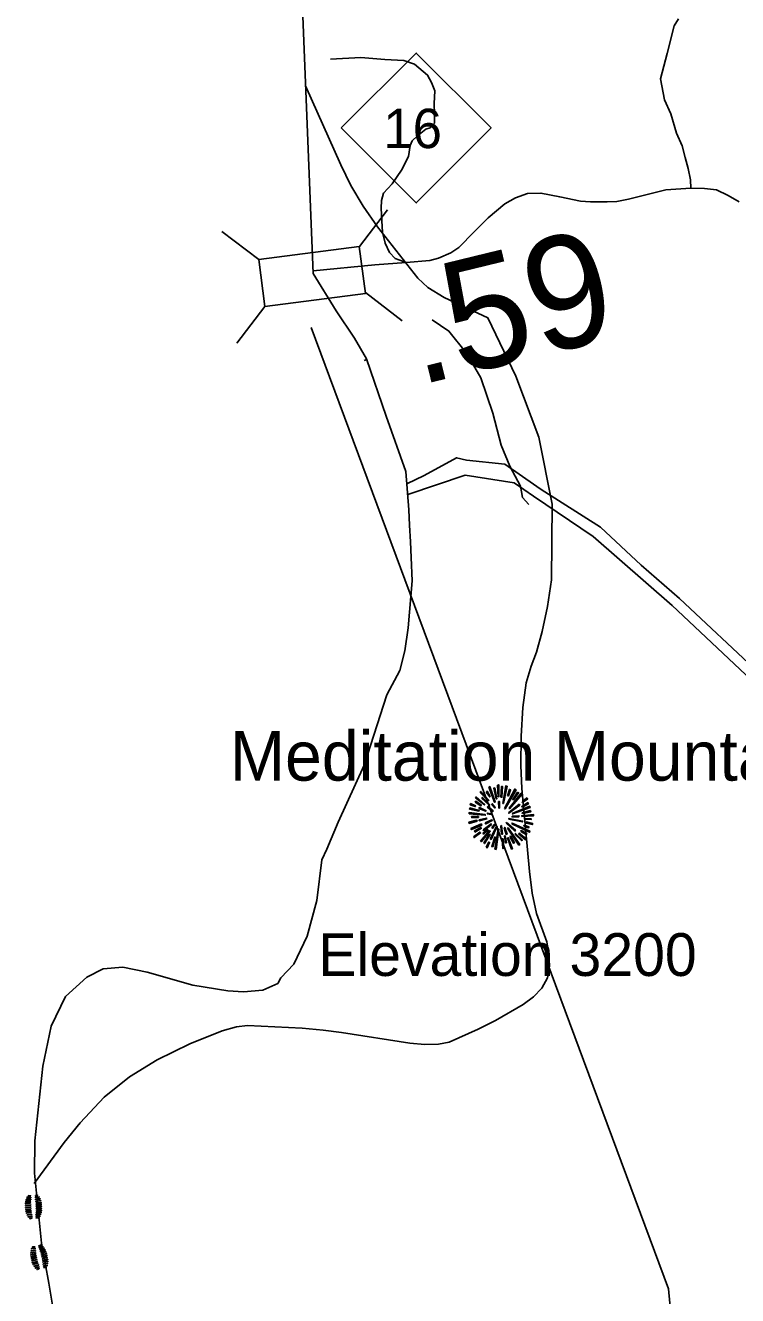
# Model space of a CAD drawing. Extents: x 1248089 to 1457196, y 820910 to 988753.
# Drawn here: x 1302535 to 1305699, y 936672 to 942316 of the extents above; entities that cross this region are included whole.
import ezdxf

# ---------------------------------------------------------------- set-up
doc = ezdxf.new("R2010")
doc.units = 0
for name, color, linetype in [('Exist Boundary Political CountyLine', 7, 'Continuous'), ('Exist Geographical Mountain Gap CELL', 7, 'Continuous'), ('Exist Geographical Mountain Summit CELL', 7, 'Continuous'), ('Exist Geographical Mountain Summit Elevation Number Label', 7, 'Continuous'), ('Exist Geographical Mountain Summit Label', 7, 'Continuous'), ('Exist Hydrographic Misc Water Feature', 7, 'Continuous'), ('Exist Road Blue Ridge Parkway', 7, 'Continuous'), ('Exist Road Blue Ridge Parkway Structure', 7, 'Continuous'), ('Exist Road Blue Ridge Parkway Structure Label', 7, 'Continuous'), ('Exist Road Non-System Type 51', 7, 'Continuous'), ('Exist Road Primary NC Attributed', 7, 'Continuous'), ('Exist Road Primary NC Shield CELL', 7, 'Continuous'), ('Exist Road Primary NC Shield Number Label', 7, 'Continuous'), ('Exist Utilities Electrical Transmission Line', 7, 'Continuous'), ('Prop CMT Slope Fill', 7, 'Continuous')]:
    doc.layers.add(name, color=color, linetype=linetype)

msp = doc.modelspace()

# ---------------------------------------------------------------- linework, layer by layer
at = {"layer": 'Exist Boundary Political CountyLine'}
for points in [[(1303813.5, 941214.4), (1303141.5, 957948.5)], [(1302662.3, 936594.3), (1302639.3, 936727.1), (1302606.5, 936905.1), (1302575.3, 937216), (1302577, 937359.5), (1302612.8, 937691.5), (1302649, 937869.2), (1302714.1, 938000.5), (1302808.3, 938087.4), (1302880.7, 938123.7), (1302967.7, 938130.9), (1303076.9, 938109.4), (1303279.2, 938051.2), (1303435, 938027), (1303503.8, 938022.2), (1303590.8, 938029.5), (1303656, 938058.4), (1303670.5, 938083.5), (1303728.4, 938145.4), (1303786.4, 938268.6), (1303829.8, 938428.1), (1303851.6, 938609.2), (1303874.1, 938655.2), (1303924, 938775.9), (1304039.9, 939029.6), (1304141.4, 939341.2), (1304199.3, 939449.9), (1304221.1, 939536.9), (1304235.3, 939639.6), (1304253.7, 939848.5), (1304248.5, 939951.5), (1304246.1, 940021.6), (1304241.8, 940095.8), (1304239.4, 940163.9), (1304224.7, 940334.1), (1304137.8, 940580.5), (1304050.8, 940834.2), (1303996.9, 940926), (1303915.7, 941047.9), (1303813.5, 941214.4)]]:
    msp.add_lwpolyline(points, dxfattribs=at)
at = {"layer": 'Exist Geographical Mountain Gap CELL'}
for points in [[(1302543.1, 937109.7), (1302542.4, 937109.7), (1302542.5, 937108), (1302558.4, 937107.2), (1302559.1, 937107.2), (1302559, 937108.9)], [(1302558.7, 937114.1), (1302558.6, 937115.8), (1302548.7, 937116.8), (1302548.8, 937115.1)], [(1302579.4, 937116.4), (1302579.4, 937114.6), (1302584.5, 937116), (1302589.7, 937117.3), (1302589.6, 937119), (1302584.5, 937117.7)], [(1302595.4, 937109.9), (1302596.2, 937109.9), (1302596.1, 937111.6), (1302580.3, 937109.3), (1302579.6, 937109.3), (1302579.7, 937107.6)], [(1302558.4, 937082.6), (1302558.3, 937084.4), (1302535.3, 937083), (1302535.4, 937081.3)], [(1302558.9, 937074), (1302558.8, 937075.8), (1302535.8, 937074.4), (1302535.9, 937072.7)], [(1302559.4, 937065.3), (1302559.3, 937067), (1302536.3, 937065.6), (1302536.4, 937063.9)], [(1302558.7, 937089.7), (1302558.6, 937091.4), (1302536.5, 937091.9), (1302536.6, 937090.1)], [(1302559.9, 937056.6), (1302559.8, 937058.4), (1302536.8, 937057), (1302536.9, 937055.3)], [(1302559.6, 937098.5), (1302559.5, 937100.2), (1302539.2, 937100.7), (1302539.3, 937099)], [(1302579.9, 937100.7), (1302580, 937099), (1302600.2, 937101.4), (1302600.1, 937103.1)], [(1302581.7, 937092), (1302581.7, 937090.3), (1302603.7, 937092.8), (1302603.6, 937094.5)], [(1302582.6, 937085.1), (1302582.7, 937083.3), (1302605.7, 937084.2), (1302605.6, 937085.9)], [(1302582.9, 937076.3), (1302583, 937074.6), (1302606, 937075.4), (1302606, 937077.1)], [(1302583.2, 937067.7), (1302583.3, 937066), (1302606.3, 937066.8), (1302606.3, 937068.5)], [(1302583.6, 937058.9), (1302583.6, 937057.2), (1302606.6, 937058), (1302606.6, 937059.7)], [(1302560.5, 937047.9), (1302560.4, 937049.6), (1302537.4, 937048.2), (1302537.5, 937046.5)], [(1302561.6, 937041), (1302561.5, 937042.7), (1302539.6, 937039.7), (1302539.7, 937038)], [(1302563.5, 937032.3), (1302563.4, 937034), (1302543.3, 937031.1), (1302543.4, 937029.4)], [(1302548.2, 937022.8), (1302547.5, 937022.7), (1302547.6, 937021), (1302563.3, 937023.7), (1302564.1, 937023.7), (1302564, 937025.4)], [(1302564.5, 937016.7), (1302564.4, 937018.4), (1302559.3, 937016.9), (1302554.2, 937015.5), (1302554.3, 937013.8), (1302559.4, 937015.2)], [(1302582.3, 937034.5), (1302582.3, 937032.8), (1302602.7, 937031.8), (1302602.6, 937033.5)], [(1302598.5, 937022.8), (1302599.3, 937022.9), (1302599.2, 937024.6), (1302583.3, 937025.7), (1302582.6, 937025.7), (1302582.7, 937024)], [(1302582.8, 937018.8), (1302582.9, 937017.1), (1302592.7, 937015.8), (1302592.7, 937017.6)], [(1302583.4, 937043.2), (1302583.5, 937041.5), (1302605.5, 937040.5), (1302605.5, 937042.3)], [(1302583.9, 937050.3), (1302583.9, 937048.5), (1302607, 937049.3), (1302606.9, 937051.1)], [(1302562.4, 936881.1), (1302561.7, 936881), (1302562.1, 936879.3), (1302578, 936880.8), (1302578.7, 936881), (1302578.3, 936882.6)], [(1302577.3, 936887.7), (1302576.9, 936889.4), (1302567, 936889), (1302567.4, 936887.3)], [(1302595, 936892.9), (1302595.4, 936891.2), (1302600.1, 936893.5), (1302605, 936895.8), (1302604.6, 936897.5), (1302599.8, 936895.2)], [(1302612, 936889.6), (1302612.7, 936889.8), (1302612.3, 936891.5), (1302597.3, 936886.2), (1302596.6, 936886), (1302597, 936884.3)], [(1302598.6, 936877.6), (1302598.9, 936875.9), (1302618.3, 936882.2), (1302617.9, 936883.9)], [(1302580.8, 936863.6), (1302580.4, 936865.3), (1302558.5, 936862.5), (1302558.9, 936860.8)], [(1302581.5, 936856.5), (1302581.2, 936858.2), (1302558.6, 936853.6), (1302559, 936851.9)], [(1302580.4, 936872.4), (1302580.1, 936874), (1302559.9, 936871.6), (1302560.2, 936869.9)], [(1302583.3, 936848.1), (1302582.9, 936849.8), (1302560.4, 936845.1), (1302560.7, 936843.4)], [(1302585, 936839.5), (1302584.7, 936841.2), (1302562.1, 936836.5), (1302562.5, 936834.8)], [(1302586.8, 936831), (1302586.4, 936832.7), (1302563.9, 936828.1), (1302564.2, 936826.3)], [(1302601.9, 936869.4), (1302602.3, 936867.7), (1302623.4, 936874.4), (1302623, 936876)], [(1302604.2, 936862.8), (1302604.6, 936861.1), (1302627, 936866.3), (1302626.6, 936868)], [(1302606.2, 936854.3), (1302606.6, 936852.6), (1302629, 936857.8), (1302628.6, 936859.5)], [(1302608.1, 936845.8), (1302608.5, 936844.2), (1302631, 936849.4), (1302630.6, 936851)], [(1302610.1, 936837.3), (1302610.5, 936835.6), (1302632.9, 936840.8), (1302632.5, 936842.5)], [(1302612, 936828.9), (1302612.4, 936827.2), (1302634.9, 936832.4), (1302634.5, 936834.1)], [(1302588.6, 936822.4), (1302588.2, 936824.1), (1302565.7, 936819.5), (1302566, 936817.7)], [(1302590.7, 936815.8), (1302590.3, 936817.5), (1302569.1, 936811.3), (1302569.5, 936809.7)], [(1302593.9, 936807.5), (1302593.5, 936809.2), (1302574, 936803.4), (1302574.3, 936801.7)], [(1302580.1, 936795.8), (1302579.4, 936795.7), (1302579.7, 936794), (1302594.9, 936798.9), (1302595.6, 936799), (1302595.2, 936800.7)], [(1302597, 936792.1), (1302596.7, 936793.8), (1302591.9, 936791.6), (1302587, 936789.4), (1302587.3, 936787.8), (1302592.2, 936789.9)], [(1302612.9, 936821.8), (1302613.3, 936820.2), (1302635.2, 936823.4), (1302634.8, 936825.1)], [(1302613.5, 936813.1), (1302613.9, 936811.4), (1302634, 936814.3), (1302633.7, 936816)], [(1302631.7, 936804.7), (1302632.4, 936804.9), (1302632, 936806.6), (1302616.2, 936804.7), (1302615.5, 936804.5), (1302615.9, 936802.9)], [(1302617.1, 936797.8), (1302617.4, 936796.1), (1302627.3, 936796.8), (1302626.9, 936798.4)]]:
    msp.add_lwpolyline(points, close=True, dxfattribs=at)
at = {"layer": 'Exist Geographical Mountain Summit CELL'}
for points in [[(1304593.4, 938931.4), (1304619.6, 938864.5), (1304622.5, 938865.5), (1304598.5, 938933.9)], [(1304627.2, 938879.4), (1304629.7, 938880.1), (1304620.7, 938928.1), (1304616.3, 938927)], [(1304631.9, 938940.8), (1304636, 938888.8), (1304639.2, 938889.2), (1304637.8, 938941.9)], [(1304648, 938886.7), (1304651.9, 938886.7), (1304655.5, 938933.9), (1304650.1, 938933.9)], [(1304659.9, 938858.3), (1304674.8, 938935.3), (1304669.3, 938937.1), (1304656.6, 938859)], [(1304663.2, 938836.5), (1304666.1, 938834.7), (1304714.8, 938919.3), (1304709.3, 938923)], [(1304677.7, 938893.5), (1304681, 938892.4), (1304690.4, 938919.3), (1304685.7, 938921.1)], [(1304511.7, 938853.6), (1304534.1, 938844.9), (1304535.3, 938847.8), (1304513.1, 938858.7)], [(1304533.5, 938864.5), (1304559.2, 938848.1), (1304561.4, 938850.7), (1304536.3, 938868.5)], [(1304534.5, 938883.4), (1304574.1, 938852.8), (1304576.3, 938855), (1304538.2, 938887.8)], [(1304554.9, 938908.1), (1304590.8, 938870.7), (1304594.2, 938873.2), (1304558.9, 938912.8)], [(1304562.9, 938880.4), (1304595.6, 938851.4), (1304597.8, 938853.6), (1304565.8, 938885.6)], [(1304582.5, 938909.6), (1304598.1, 938887.8), (1304599.9, 938889.2), (1304586.5, 938913.6)], [(1304606.1, 938855), (1304620, 938838.6), (1304622.1, 938840.8), (1304609.4, 938858)], [(1304637.4, 938867.4), (1304638.8, 938838.3), (1304641.4, 938838.6), (1304641.4, 938867.7)], [(1304684.2, 938837.9), (1304686.4, 938835.8), (1304742, 938900.1), (1304738, 938904.8)], [(1304721.7, 938909.6), (1304700.6, 938876.1), (1304703.5, 938875), (1304726, 938906.3)], [(1304742, 938843.1), (1304769.6, 938858), (1304766.7, 938863), (1304740.6, 938845.6)], [(1304742, 938865.9), (1304743.9, 938863.4), (1304766.7, 938879.7), (1304763.1, 938883.4)], [(1304506.1, 938813.2), (1304578.1, 938806.3), (1304578.5, 938809.2), (1304506.1, 938818.3)], [(1304508.7, 938834.3), (1304550.2, 938824.8), (1304551.3, 938828.1), (1304509.9, 938839)], [(1304550.2, 938836.5), (1304580.7, 938824.5), (1304581.8, 938826.6), (1304552.4, 938840.5)], [(1304586.5, 938841.9), (1304611.6, 938823), (1304613.7, 938825.9), (1304589, 938845.2)], [(1304586.8, 938812.2), (1304603.9, 938809.9), (1304604.3, 938812.2), (1304587.6, 938816.5)], [(1304681, 938818), (1304682.8, 938815.4), (1304731.5, 938851.4), (1304728.3, 938855.8)], [(1304697, 938802.4), (1304697, 938799.5), (1304727.1, 938799.5), (1304727.9, 938804.5)], [(1304698, 938815.1), (1304699.1, 938812.8), (1304777.3, 938841.5), (1304775.5, 938846.3)], [(1304740.2, 938801.3), (1304792.6, 938804.5), (1304792.9, 938809.2), (1304740.6, 938804.5)], [(1304743.9, 938815.1), (1304780.6, 938821.6), (1304779.1, 938827), (1304742.4, 938817.3)], [(1304504.7, 938775.5), (1304506.1, 938770.3), (1304542.2, 938780.9), (1304540, 938784.2)], [(1304514.5, 938747.8), (1304517.1, 938743.1), (1304562.5, 938763.1), (1304561, 938767.8)], [(1304518.2, 938795.8), (1304548, 938797.3), (1304548, 938800.9), (1304517.1, 938800.9)], [(1304532, 938731.9), (1304561, 938748.6), (1304558.9, 938752.2), (1304529.8, 938736.9)], [(1304550.6, 938786.8), (1304551.6, 938782), (1304584.7, 938790.4), (1304584, 938794)], [(1304568.3, 938741.3), (1304571.2, 938737.6), (1304605.7, 938766), (1304603.9, 938768.5)], [(1304578.1, 938772.5), (1304580.4, 938767.8), (1304609.1, 938783), (1304608, 938786.4)], [(1304599.9, 938701.3), (1304604.3, 938699.5), (1304630.9, 938758), (1304628.3, 938758.8)], [(1304606.9, 938750.7), (1304610.1, 938747.8), (1304620.3, 938764.2), (1304618.4, 938765.6)], [(1304621.4, 938655.9), (1304626.1, 938654.8), (1304638.8, 938744.1), (1304635.6, 938744.9)], [(1304646.8, 938759.8), (1304650.8, 938722.8), (1304655.2, 938723.1), (1304650.1, 938760.6)], [(1304662.9, 938751.1), (1304671.5, 938721.3), (1304675.5, 938723.1), (1304665, 938752.2)], [(1304671.2, 938771.5), (1304709.7, 938736.2), (1304712.2, 938740.5), (1304673, 938773.7)], [(1304677.4, 938748.9), (1304727.9, 938674.1), (1304731.5, 938676.9), (1304679.9, 938750)], [(1304682.4, 938788.6), (1304743.2, 938776.6), (1304744.2, 938780.9), (1304683.5, 938792.2)], [(1304696.2, 938768.9), (1304774.4, 938730.7), (1304776.2, 938736.2), (1304697.7, 938771.8)], [(1304749.7, 938758.8), (1304770.7, 938750.7), (1304772.5, 938755.1), (1304751.1, 938762)], [(1304755.1, 938789.3), (1304781.6, 938787), (1304781.6, 938791.4), (1304755.5, 938792.5)], [(1304759.2, 938772.1), (1304787.4, 938764.9), (1304788.2, 938770.3), (1304760.2, 938776.6)], [(1304525.8, 938711.1), (1304528.7, 938707.1), (1304557.1, 938728.2), (1304554.5, 938731.5)], [(1304556.7, 938691.5), (1304559.6, 938689), (1304600.3, 938736.6), (1304597.4, 938738.7)], [(1304572, 938722.8), (1304591.2, 938740.9), (1304587.9, 938743.1), (1304567.6, 938726)], [(1304596.7, 938722.8), (1304571.6, 938683.5), (1304574.8, 938681), (1304600.7, 938720.6)], [(1304611.6, 938666.1), (1304623.6, 938708.9), (1304620, 938709.3), (1304607.2, 938667.1)], [(1304653, 938701.3), (1304656.6, 938658.8), (1304660.7, 938659.8), (1304657.3, 938701.3)], [(1304672.6, 938684.6), (1304667.2, 938714.4), (1304663.9, 938714.4), (1304668.3, 938683.5)], [(1304677.4, 938706.1), (1304694.8, 938656.2), (1304699.1, 938658), (1304680.3, 938706.8)], [(1304687.8, 938711.8), (1304703.9, 938682.4), (1304707.9, 938684.6), (1304691.6, 938713.3)], [(1304709.7, 938723.1), (1304739.8, 938694), (1304743.2, 938696.6), (1304711.9, 938725.6)], [(1304726.4, 938723.8), (1304756.9, 938698), (1304760.2, 938701.7), (1304728.3, 938726.4)], [(1304735.5, 938734.8), (1304760.6, 938721.7), (1304763.1, 938725.3), (1304737.7, 938738.7)], [(1304581.8, 938664.2), (1304586.5, 938661.4), (1304597.4, 938686), (1304594.2, 938688.2)]]:
    msp.add_lwpolyline(points, close=True, dxfattribs=at)
at = {"layer": 'Exist Hydrographic Misc Water Feature'}
msp.add_lwpolyline([(1302574.8, 937170.6), (1302708.1, 937352.4), (1302778, 937440.3), (1302885, 937554.1), (1302997.1, 937644.5), (1303121.1, 937720.3), (1303266, 937790.2), (1303409.1, 937848.3), (1303473, 937866.8), (1303522, 937872.2), (1303764.1, 937860), (1303858.1, 937852.2), (1303940, 937841.8), (1304243.1, 937793.5), (1304310.1, 937788), (1304370.1, 937788.8), (1304418.1, 937798.3), (1304546.1, 937855.8), (1304623.1, 937894.7), (1304747.1, 937966.3), (1304792.1, 937999.6), (1304829.1, 938038.3), (1304854.1, 938084.3), (1304864.1, 938136), (1304861.1, 938191.3), (1304851.1, 938244.5), (1304806.1, 938369.8), (1304787.1, 938460.9), (1304774.1, 938556.3), (1304740, 938925.7), (1304736.1, 939028.3), (1304737.1, 939157.8), (1304745.1, 939285.5), (1304760, 939394.5), (1304782.1, 939468.3), (1304806.1, 939531.5), (1304831.1, 939623.6), (1304854.1, 939734), (1304872.1, 939852.3), (1304876.1, 940188.5), (1304816.1, 940486), (1304714.1, 940757.5), (1304590.1, 941016.3), (1304396.1, 941107.3), (1304323.1, 941151), (1304278.1, 941192.3), (1304100.1, 941420.8), (1304036, 941512.3), (1303981, 941604.8), (1303936, 941696.9), (1303780, 942047.9)], dxfattribs=at)
at = {"layer": 'Exist Road Blue Ridge Parkway'}
msp.add_line((1303813.5, 941214.5), (1303813.5, 941214.5), dxfattribs=at)
at = {"layer": 'Exist Road Blue Ridge Parkway Structure'}
for p, q in [((1304018.9, 941333.4), (1304144.1, 941496.6)), ((1303408.6, 941400.8), (1303571.9, 941275.5)), ((1304045.7, 941129.4), (1304209, 941004.1)), ((1303474.1, 940903.5), (1303599.4, 941066.8))]:
    msp.add_line(p, q, dxfattribs=at)
msp.add_lwpolyline([(1303571.9, 941275.5), (1304018.7, 941334.3), (1304046.2, 941125.6), (1303599.4, 941066.8)], close=True, dxfattribs=at)
at = {"layer": 'Exist Road Blue Ridge Parkway Structure Label'}
msp.add_lwpolyline([(1303804.3, 940973.6), (1305392.4, 936702), (1305611.5, 934347.1), (1304899.6, 931827.9)], dxfattribs=at)
at = {"layer": 'Exist Road Non-System Type 51'}
msp.add_line((1304051.7, 940831.7), (1304040.7, 940826.9), dxfattribs=at)
for points in [[(1305436.7, 942345), (1305416.8, 942314.5), (1305386.3, 942190.9), (1305357.4, 942078), (1305374.1, 941984.9)], [(1304226.5, 941262.8), (1304178.5, 941280.8), (1304152.6, 941306.8), (1304132.8, 941348), (1304122.1, 941396.8), (1304119.1, 941447.2), (1304116, 941503.7), (1304117.5, 941538.7), (1304126.7, 941570.8), (1304164.8, 941612), (1304206, 941673), (1304236.5, 941734.1), (1304244.1, 941782.9), (1304253.2, 941802.8), (1304277.6, 941825.6), (1304314.2, 941854.6), (1304334, 941861.6), (1304352.3, 941881.4), (1304352.3, 941921.1), (1304350.8, 941968.4), (1304353.8, 942024.9), (1304340.1, 942063), (1304321.8, 942095.1), (1304264.3, 942144.4), (1304216.7, 942160.2), (1304131.7, 942164.5), (1304026, 942172.9), (1303890.8, 942166.2)], [(1305374.1, 941984.9), (1305403.1, 941923), (1305427.5, 941837.5), (1305453.4, 941781.1), (1305465.6, 941729.2), (1305479.3, 941680.4), (1305490, 941630), (1305491.2, 941593.2)], [(1304772.4, 940187.4), (1304743.9, 940218.6), (1304734.5, 940268.9), (1304687.3, 940357), (1304649.6, 940451.5), (1304611.8, 940593.1), (1304558.4, 940750.4), (1304495.5, 940860.5), (1304416.9, 940958.1), (1304342.9, 941008.5)]]:
    msp.add_lwpolyline(points, dxfattribs=at)
at = {"layer": 'Exist Road Primary NC Attributed'}
msp.add_lwpolyline([(1305706.6, 941531.6), (1305657.6, 941561), (1305605.9, 941584.8), (1305552.7, 941591.8), (1305491.2, 941593.2), (1305380.7, 941584.8), (1305214.2, 941544.2), (1305162.5, 941534.4), (1305120, 941532.9), (1305046.4, 941531.6), (1305001.4, 941535.8), (1304909, 941554), (1304825.1, 941570.8), (1304766.4, 941569.4), (1304713.2, 941549.8), (1304665.7, 941523.2), (1304591.6, 941461.6), (1304528.6, 941398.6), (1304460.1, 941330), (1304425.1, 941306.2), (1304370.6, 941282.4), (1304331.4, 941271.2), (1304226.5, 941262.8), (1304087, 941251.8), (1303813.1, 941224.9)], dxfattribs=at)
at = {"layer": 'Exist Road Primary NC Shield CELL'}
msp.add_lwpolyline([(1303938.4, 941860.5), (1304271.4, 942193.5), (1304604.4, 941860.5), (1304271.4, 941527.5)], close=True, dxfattribs=at)
at = {"layer": 'Exist Utilities Electrical Transmission Line'}
for p, q in [((1304665.7, 940367), (1304807.8, 940267.2)), ((1304706, 940282.9), (1304793.2, 940223.8))]:
    msp.add_line(p, q, dxfattribs=at)
for points in [[(1304229.5, 940278.5), (1304307.1, 940316.4), (1304450.9, 940395.2), (1304495, 940383.7), (1304665.7, 940367)], [(1304233.6, 940231.2), (1304488.8, 940318.3), (1304706, 940282.9)], [(1304793.2, 940223.8), (1305057.1, 940044.8), (1305408.4, 939738.3), (1305758.8, 939407.9), (1306081.4, 939078.2), (1306341.1, 938867.2)], [(1304807.8, 940267.2), (1304826, 940254.4), (1305090.2, 940085.9), (1305270.3, 939917.6), (1305441, 939769.5), (1305795.6, 939437.2), (1305964, 939301)]]:
    msp.add_lwpolyline(points, dxfattribs=at)

# ---------------------------------------------------------------- texts
at = {"layer": 'Exist Geographical Mountain Summit Elevation Number Label'}
msp.add_text('Elevation 3200', height=190, dxfattribs=at).set_placement((1303836.6, 938092.6))
at = {"layer": 'Exist Geographical Mountain Summit Label'}
msp.add_text('Meditation Mountain', height=220, dxfattribs=at).set_placement((1303443.5, 938960.3))
at = {"layer": 'Exist Road Primary NC Shield Number Label'}
msp.add_text('16', height=175, dxfattribs=at).set_placement((1304125.5, 941770.8))
at = {"layer": 'Prop CMT Slope Fill'}
msp.add_text('.59', height=500, rotation=13.7069, dxfattribs=at).set_placement((1304279.8, 940715.5))

doc.saveas('drawing.dxf')
